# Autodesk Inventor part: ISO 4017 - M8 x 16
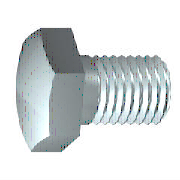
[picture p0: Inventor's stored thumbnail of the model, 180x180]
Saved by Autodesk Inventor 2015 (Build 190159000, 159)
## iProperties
Created: 2014-02
Part Number: ISO 4017 - M8 x 16
Material: Aço inoxidável, 440C
Description: Parafusos de cabeça sextavada
Document SubType Name: Modeling
Standard: ISO 4017
Designer: Andrew Almeida
Standard Revision: Third edition 1999-08-15
Standards Organization: ISO
Language: pt-BR
Size Designation: M8 x 16
Categories: <MemberInstance><Categories><Category DisplayName="Parafusos" InternalName="e4da775c-781d-43d5-af7c-5136215cf5a6" Mnemonic="FSTN"><Category DisplayName="Parafus
Density: 7.75 g/cm^3
Appearance: Semi-polido
IsCustomPart: 1
Author: Andrew Almeida
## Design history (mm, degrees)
sketch "Rascunho1"
  geometry: L1 (0, 5.815)-(0, 4); L2 (4, 4)-(16, 4); L3 (16, 4)-(16, 0); L4 (16, 0)-(-0.6, 0); L5 (-3.92, 0)-(19.32, 0) reference; L6 (-0.6, 0)-(-0.6, 5.815); L7 (-0.6, 5.815)-(0, 5.815); L8 (4, 4)-(3.233, 4); L9 (3.233, 4)-(0, 4); L10 (0, -1.163)-(0, 6.978) reference
  constraints: 16 end point, 2 collinear, 2 perpendicular, 1 parallel
  dimensions: "d0" = 16 distance between parallel lines of L3 L1 (= NLG); "d1" = 12 distance from line of L2.start L3 (= GEL); "d2" = 8 diameter of L2 L4 (= GD); "d9" = 0.6001 distance between parallel lines of L6 L1 (computed from SD); "d10" = 11.63 diameter of L7 L4 (= SD2); "d13" = 0.76691 distance of L2.start L8.end (computed from GAL); "d14" = 8 diameter of L9 L4 (= BDM)
revolve "Corpo" sketch "Rascunho1" stored, may be unused: angle "d12" = 90 deg
sketch "Rascunho2"
  geometry: L1 (0, 7.506)-(6.5, 3.753); L2 (6.5, 3.753)-(6.5, -3.753); L3 (6.5, -3.753)-(0, -7.506); L4 (0, -7.506)-(-6.5, -3.753); L5 (-6.5, -3.753)-(-6.5, 3.753); L6 (-6.5, 3.753)-(0, 7.506); 2 further points
  constraints: 12 end point, 1 coincident, 1 vertical, 11 other
  dimensions: "d11" = 13 distance between parallel lines of L5 L2 (= SW)
extrude "Cabeça" join sketch "Rascunho2" distance "d3" = 4.7 (= KOH - SD); taper "d4" = 0 deg
sketch "Rascunho4"
  geometry: L1 (-5.3, 6.5)-(-5.3, 7.506); L2 (-5.3, 7.506)-(-4.72, 7.506); L3 (-4.72, 7.506)-(-5.3, 6.5); L4 (-6.24, 0)-(0.34, 0) reference; L5 (-0.6, 7.506)-(-5.3, 7.506) reference; L6 (-5.3, 3.753)-(-5.3, 7.506) reference
  constraints: 6 end point, 2 collinear, 1 perpendicular, 1 vertical
  dimensions: "d5" = 30 deg angle of L3 L1 (= ANG1); "d19" = 13 diameter of L1.start L4 (= SW0)
revolve "Chanfrar1" sketch "Rascunho4" stored, may be unused: angle "d21" = 90 deg
chamfer "Chanfrar2" distance "d6" = 0.76681 (= -0.5 x SPD + 0.5 x GD); stored, may be unused: second distance "d7" = 0.76691 (computed from GUL), angle "d55" = 45 deg
workplane "Work Plane1"
body "Solid1"
feature "Rosca" dims "d15" = 12 (= GEL), "d16" = 0
other parameters: "NLG" = 16 [user parameter; used in 1 equation term], "GD" = 8 (= NND) [user parameter; used in 2 equation terms], "BDM" = 8 (= NND) [user parameter; used in 1 equation term], "KOH" = 5.3 [user parameter; used in 1 equation term], "GEL" = 12 [user parameter; used in 2 equation terms], "SW" = 13 [user parameter; used in 2 equation terms], "SW0" = 13 (= SW) [user parameter; used in 1 equation term], "SPD" = 6.46637 (= NND - 1.2269 x PTC) [user parameter; used in 1 equation term], "SD2" = 11.63 [user parameter; used in 2 equation terms], "SD" = 0.6 [user parameter; used in 2 equation terms], "ANG1" = 30 deg [user parameter; used in 1 equation term], "GAL" = 0.76681 (= 0.61345 x PTC) [user parameter; used in 1 equation term], "GUL" = 0.76681 (= 0.61345 x PTC) [user parameter; used in 1 equation term], "d8" = 0, "RR" = 0.4 [user parameter], "d57" = 0, "d58" = 0, "TPU" = 8 (computed from PTC) [user parameter], "GD1" = 6.46637 (= THREADDIA - 1.2269 x PTC) [user parameter], "THREADDIA" = 8 [user parameter; used in 1 equation term], "SDH" = 11.63 (= SD2) [user parameter], "SDHG" = 4 [user parameter], "TOA" = 30 deg [user parameter], "PTC" = 1.25 [user parameter; used in 5 equation terms], "NND" = 8 [user parameter; used in 3 equation terms], "E0" = 15.015 [user parameter]
